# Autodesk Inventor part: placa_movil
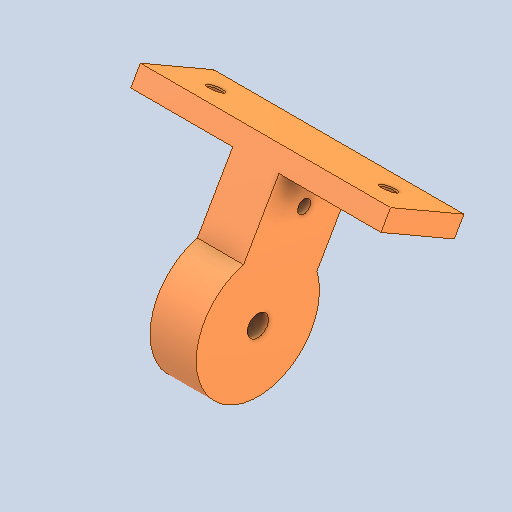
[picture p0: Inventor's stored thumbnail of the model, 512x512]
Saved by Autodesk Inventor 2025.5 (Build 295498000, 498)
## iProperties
Created: 2026-10
Part Number: placa_movil
Material: Genérico
Document SubType Name: Modeling
Designer: Luis M
Density: 1 g/cm^3
Appearance: Valor por defecto
Author: Luis M
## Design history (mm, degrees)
feature "Base1"
node "Sólido1"
